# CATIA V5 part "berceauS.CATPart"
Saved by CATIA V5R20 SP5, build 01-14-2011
Part number: berceauS
Publications: "Plan.1", "hauteur plateau", "Point.1", "Plan.2", "Droite.1", "Droite.2", "Point.2", "Point.3", "Point.4", "eloignement axe", "ecartement axe", "largeur levier", "Y colonne", "X colonne", "Plan.4", "Plan.3", "Point.5", "décalage base", "écartement jambe", "hauteur roues ar", "éloignement roues ar", "décalage poche pour jambe", "longueur jambe", "implentation verin2", "longueur tige verin2"
Bounding box of the stored display mesh (mm): x -100 to 100, y -150 to 0, z 0 to 1350
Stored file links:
  U:\think motion\fin\berceauS.CATPart
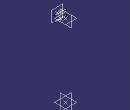
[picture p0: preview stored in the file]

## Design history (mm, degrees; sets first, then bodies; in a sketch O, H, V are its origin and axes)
Parameters
  `hauteur plateau` = 1300 mm
  `eloignement axe` = 60 mm
  `ecartement axe` = 50 mm
  `largeur levier` = 40 mm
  `X colonne` = 200 mm
  `Y colonne` = 1000 mm
  `décalage plateau` = 150 mm
  `décalage base` = 40 mm
  `écartement jambe` = 650 mm
  `éloignement roues ar` = 220 mm
  `hauteur roues ar` = 40 mm
  `décalage poche pour jambe` = 10 mm
  `longueur jambe` = 1000 mm
  `implentation verin2` = 130 mm
  `longueur tige verin2` = 200 mm
Set1
  Plane1: type Offset, RefPlane xy-plane, Offset 1300 {= `hauteur plateau`}
  Point1: (0, 0, 0)
  Plane2: type Angle, RefPlane Plane1, Direction Y axis, Angle 90
  Point2: type OnPlane, Support Plane2, RefPoint Point5, H 60 {= `eloignement axe`}, V 50 {= `ecartement axe`}, Direction (0, 1, 0)
  Point3: type OnPlane, Support Plane1, H 0, V 0, Direction (1, 0, 0)
  Line1: type PtDir, RefPoint Point2, Direction Plane2, Start -100, End 100
  Point4: type OnPlane, Support Plane2, RefPoint Point5, H 60 {= `eloignement axe`}, V -50 {= -`ecartement axe`}, Direction (0, 1, 0)
  Line2: type PtDir, RefPoint Point4, Direction Plane2, Start -100, End 100
  Plane3: type Angle, RefPlane Plane1, Direction X axis, Angle 90
  Plane4: type Offset, RefPlane Plane3, Offset 150 {= `décalage plateau`}
  Point5: type OnPlane, Support Plane4, RefPoint Point3, H 0, V 0, Direction (1, 0, 0)
Body1 (main body)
